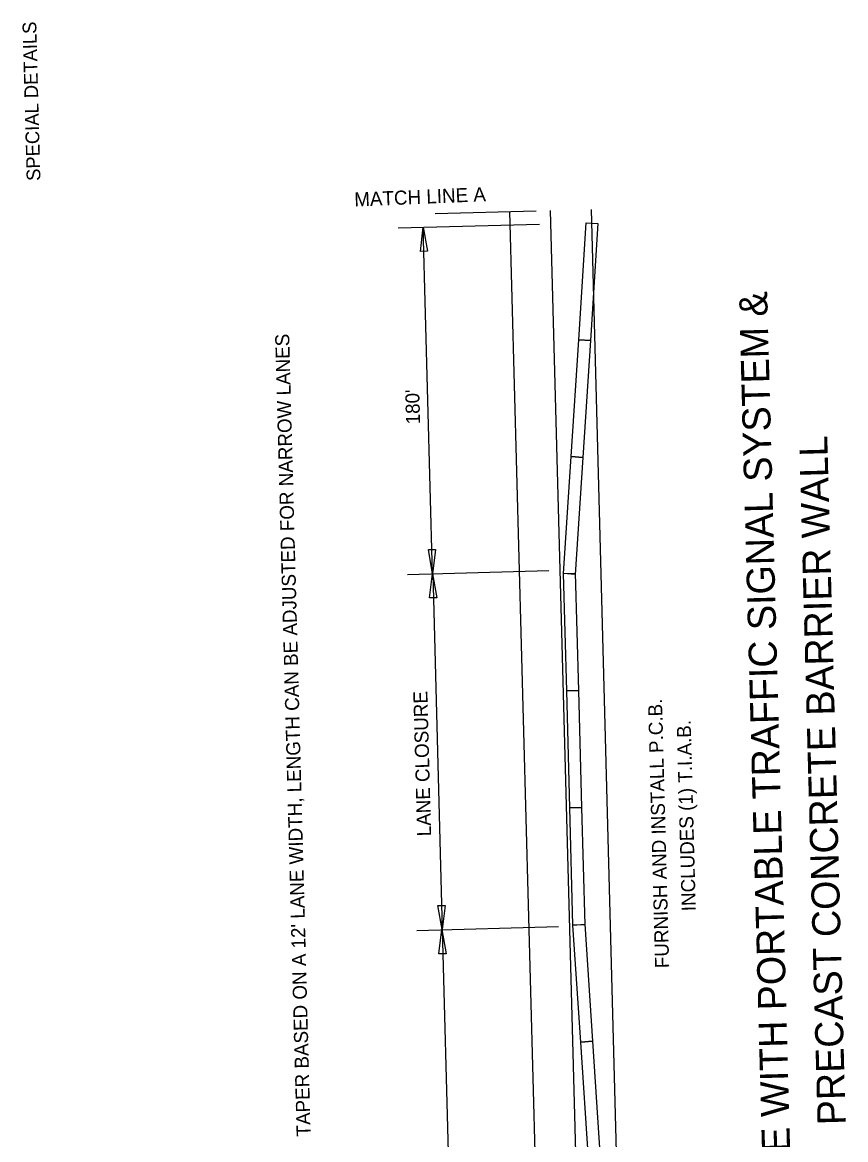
# Model space of a CAD drawing. Extents: x 1929624 to 1932072, y 596315 to 605954.
# Drawn here: x 1930711.6 to 1931062.8, y 597266 to 597742.7 of the extents above; entities that cross this region are included whole.
import ezdxf

# ---------------------------------------------------------------- set-up
doc = ezdxf.new("R2010")
doc.units = 0
for name, color, linetype in [('B_Concrete', 7, 'Continuous'), ('B_Existing Ground', 7, 'Continuous'), ('Default', 7, 'Continuous'), ('T_Vehicle Path Rt', 7, 'Continuous')]:
    doc.layers.add(name, color=color, linetype=linetype)

msp = doc.modelspace()

# ---------------------------------------------------------------- linework, layer by layer
at = {"layer": 'Default'}
for p, q in [((1930887.73, 597661.11), (1930930.77, 597662.27)), ((1930937.4, 596998.85), (1930919.6, 597661.97)), ((1930954.78, 596999.31), (1930936.98, 597662.44)), ((1930972.16, 596999.78), (1930954.36, 597662.9)), ((1930871.91, 597655.05), (1930932.24, 597656.67)), ((1930881.42, 597645), (1930882.69, 597655.34)), ((1930886.66, 597507.5), (1930882.69, 597655.34)), ((1930882.69, 597655.34), (1930884.51, 597645.08)), ((1930884.51, 597645.08), (1930881.42, 597645)), ((1930884.84, 597517.76), (1930887.93, 597517.84)), ((1930886.66, 597507.5), (1930884.84, 597517.76)), ((1930887.93, 597517.84), (1930886.66, 597507.5)), ((1930875.88, 597507.21), (1930936.2, 597508.83)), ((1930885.39, 597497.16), (1930886.66, 597507.5)), ((1930886.66, 597507.5), (1930888.48, 597497.24)), ((1930886.79, 597507.51), (1930890.74, 597355.62)), ((1930888.48, 597497.24), (1930885.39, 597497.16)), ((1930888.91, 597365.88), (1930892.01, 597365.96)), ((1930892.01, 597365.96), (1930890.74, 597355.62)), ((1930890.74, 597355.62), (1930888.91, 597365.88)), ((1930879.95, 597355.33), (1930940.28, 597356.95)), ((1930889.33, 597345.27), (1930890.6, 597355.62)), ((1930890.6, 597355.62), (1930892.43, 597345.36)), ((1930890.74, 597355.62), (1930897.44, 597105.99)), ((1930892.43, 597345.36), (1930889.33, 597345.27))]:
    msp.add_line(p, q, dxfattribs=at)
at = {"layer": 'T_Vehicle Path Rt'}
for points in [[(1930948.96, 597607.31), (1930952.18, 597657.21), (1930957.17, 597656.88), (1930953.95, 597606.99)], [(1930945.73, 597557.42), (1930948.96, 597607.31), (1930953.95, 597606.99), (1930950.72, 597557.09)], [(1930942.51, 597507.52), (1930945.73, 597557.42), (1930950.72, 597557.09), (1930947.5, 597507.2)], [(1930943.85, 597457.54), (1930942.51, 597507.52), (1930947.51, 597507.65), (1930948.85, 597457.67)], [(1930945.19, 597407.56), (1930943.85, 597457.54), (1930948.85, 597457.67), (1930950.19, 597407.69)], [(1930946.53, 597357.57), (1930945.19, 597407.56), (1930950.19, 597407.69), (1930951.53, 597357.71)], [(1930949.85, 597307.68), (1930946.53, 597357.57), (1930951.52, 597357.91), (1930954.84, 597308.02)], [(1930953.16, 597257.79), (1930949.85, 597307.68), (1930954.84, 597308.02), (1930958.15, 597258.13)]]:
    msp.add_lwpolyline(points, close=True, dxfattribs=at)

# ---------------------------------------------------------------- texts
at = {"layer": 'B_Concrete'}
msp.add_text('SPECIAL DETAILS', height=5.862, rotation=91.5377, dxfattribs=at).set_placement((1930719.38, 597675.16))
at = {"layer": 'B_Existing Ground'}
msp.add_text("TAPER BASED ON A 12' LANE WIDTH, LENGTH CAN BE ADJUSTED FOR NARROW LANES", height=6, rotation=91.5377, dxfattribs=at).set_placement((1930834.65, 597267.46))
at = {"layer": 'Default'}
for s, height, rotation, p in [('MATCH LINE A', 6, 2.3436, (1930853.35, 597664.12)), ('LANE CLOSURE WITH PORTABLE TRAFFIC SIGNAL SYSTEM &', 12, 91.5377, (1931042.21, 597147.6)), ("180'", 6, 91.5377, (1930881.33, 597571.29)), ('PRECAST CONCRETE BARRIER WALL', 12, 91.5377, (1931062.87, 597272.4)), ('LANE CLOSURE', 6, 91.5377, (1930886.05, 597395.52)), ('FURNISH AND INSTALL P.C.B. ', 6, 91.5377, (1930987.58, 597339.26)), ('INCLUDES (1) T.I.A.B.', 6, 91.5377, (1930998.93, 597363.57))]:
    msp.add_text(s, height=height, rotation=rotation, dxfattribs=at).set_placement(p)

doc.saveas('drawing.dxf')
